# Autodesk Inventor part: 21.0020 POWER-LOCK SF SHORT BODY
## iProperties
Created: 2012-06
Part Number: 21.0020 POWER-LOCK SF SHORT BODY
Document SubType Name: Modeling
Designer: Administrator
Density: 7.85 g/cm^3
Material: Steel
Mass: 10.1836 g
Surface Area: 14.6361 cm^2
Volume: 1.29727 cm^3
Author: Administrator
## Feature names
1. Base1
2. Extrusion1
3. Hole2
